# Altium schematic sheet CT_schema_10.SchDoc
size 147 x 119 mm
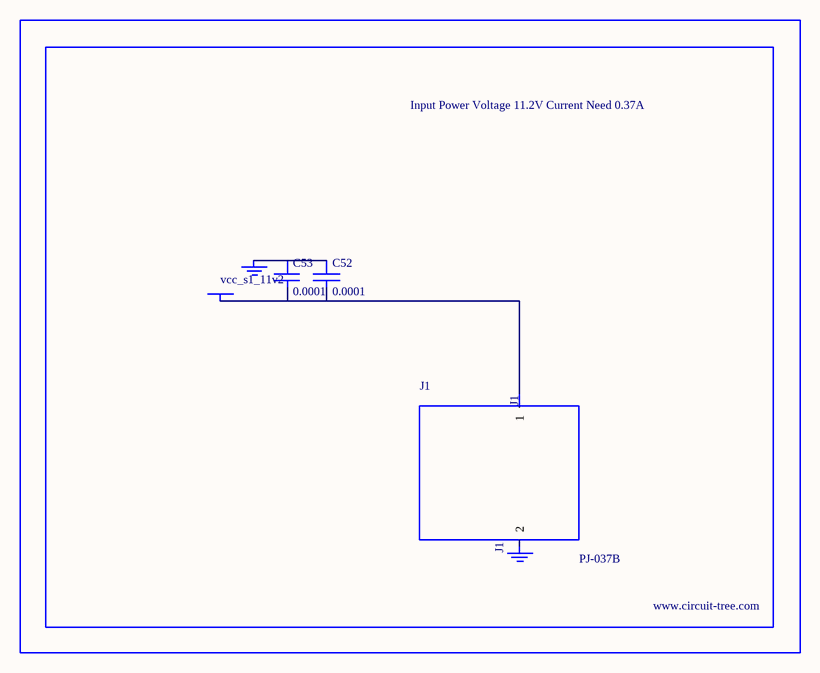
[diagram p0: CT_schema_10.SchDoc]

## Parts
BORDER9  (no value)
C52  0.0001  [EXV-9H]
C53  0.0001  [EXV-9H]
GND_INSTANCE_9_0  (no value)
GND_INSTANCE_9_1  (no value)
J1  PJ-037B  [PJ-037B_PACKAGE]
POWER_INSTANCE_9_0  vcc_s1_11v2

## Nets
NetC52_1: C52.1 C53.1 GND_INSTANCE_9_0.0(GND)
NetC52_2: C52.2 C53.2 J1.1 POWER_INSTANCE_9_0.0(PWR)

Not connected (* = marked no-connect by the designer): GND_INSTANCE_9_1 0(GND); J1 2

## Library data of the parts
BORDER9 = BORDER_PAGE9
C52 C53 = EDK107M035A9HAA
GND_INSTANCE_9_0 GND_INSTANCE_9_1 = GND
POWER_INSTANCE_9_0 = PWR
